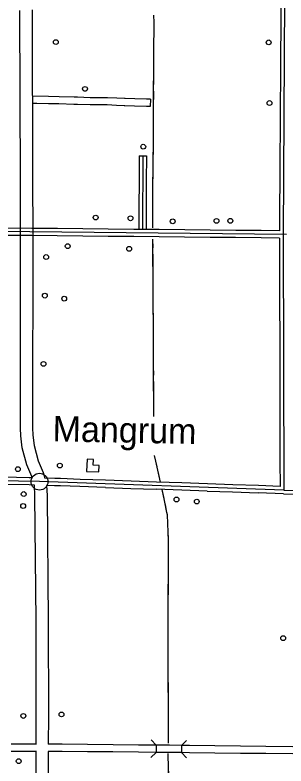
# Model space of a CAD drawing. Extents: x -4306 to 3843, y 131 to 8341.
# Drawn here: x -1173 to -274, y 4435 to 6927 of the extents above; entities that cross this region are included whole.
import ezdxf

# ---------------------------------------------------------------- set-up
doc = ezdxf.new("R2010")
doc.units = 0
for name, color, linetype in [('10', 7, 'Continuous'), ('24', 7, 'Continuous'), ('31', 7, 'Continuous'), ('32', 7, 'Continuous'), ('38', 7, 'Continuous'), ('56', 7, 'Continuous'), ('57', 7, 'Continuous'), ('60', 7, 'Continuous')]:
    doc.layers.add(name, color=color, linetype=linetype)

msp = doc.modelspace()

# ---------------------------------------------------------------- linework, layer by layer
at = {"layer": '10'}
for p, q in [((-1154.7, 6376.4), (-1156.2, 6941.8)), ((-1116.2, 6944.1), (-1114.6, 6374.8))]:
    msp.add_line(p, q, dxfattribs=at)
for points in [[(-1115.9, 5392.1), (-1117, 5396), (-1133.5, 5434.2), (-1148.9, 5491), (-1153.2, 5529.9), (-1154.3, 5556.1), (-1153.9, 6206.8), (-1154.7, 6376.4)], [(-1114.6, 6374.8), (-1113.9, 6206.9), (-1114.3, 5556.9), (-1113.3, 5533), (-1109.5, 5498.5), (-1095.6, 5447.4), (-1079.2, 5409.3), (-1073.9, 5390.1)], [(-1102.4, 4507.2), (-1102, 4600.1), (-1102.8, 4916.5), (-1106.4, 5331), (-1107.8, 5367)], [(-1067.7, 5365.9), (-1066.4, 5331.9), (-1062.8, 4916.7), (-1062, 4600.1), (-1062.4, 4507.1)], [(-1101.9, 4080.9), (-1103.3, 4295.8), (-1102.5, 4483.2)], [(-1062.5, 4483.1), (-1063.3, 4295.8), (-1061.9, 4081.1)]]:
    msp.add_lwpolyline(points, dxfattribs=at)
at = {"layer": '24'}
msp.add_circle((-1091.3, 5378.3), 28, dxfattribs=at)
at = {"layer": '31'}
for p, q in [((-1041, 5389), (-1073.9, 5390.1)), ((-1021.2, 5388.3), (-1041, 5389)), ((-956.5, 5386), (-1021.2, 5388.3)), ((-872.1, 5383.1), (-956.5, 5386)), ((-1041.8, 5365), (-1067.7, 5365.9)), ((-1022, 5364.3), (-1041.8, 5365)), ((-957.4, 5362), (-1022, 5364.3)), ((-872.9, 5359.1), (-957.4, 5362)), ((-618.8, 5374.2), (-703.2, 5377.2)), ((-534.3, 5371.2), (-618.8, 5374.2)), ((-293.5, 5362.8), (-365.5, 5365.3)), ((-704, 5353.2), (-704, 5353.2)), ((-619.6, 5350.2), (-704, 5353.2)), ((-535.2, 5347.3), (-619.6, 5350.2)), ((-366.3, 5341.3), (-366.3, 5341.3)), ((-281.9, 5338.4), (-366.3, 5341.3)), ((-281.8, 5338.4), (-244.9, 5337.3))]:
    msp.add_line(p, q, dxfattribs=at)
for points in [[(-872.9, 5359.1), (-788.5, 5356.1)], [(-787.6, 5380.1), (-872.1, 5383.1)], [(-703.2, 5377.2), (-787.6, 5380.1)], [(-449.9, 5368.3), (-534.3, 5371.2)], [(-365.5, 5365.3), (-449.9, 5368.3)], [(-788.5, 5356.1), (-704, 5353.2)], [(-535.2, 5347.3), (-450.7, 5344.3)], [(-450.7, 5344.3), (-366.3, 5341.3)]]:
    msp.add_lwpolyline(points, dxfattribs=at)
at = {"layer": '32'}
for p, q in [((-277.8, 7052), (-283.5, 6198.8)), ((-290.4, 6967.6), (-290.9, 6883.1)), ((-290.9, 6883.1), (-291.5, 6798.6)), ((-291.5, 6798.6), (-292, 6714.1)), ((-292, 6714.1), (-292.6, 6629.7)), ((-1061.1, 6656.6), (-1115.4, 6657.9)), ((-1026, 6655.7), (-1061.1, 6656.6)), ((-976.6, 6654.2), (-1026, 6655.7)), ((-965, 6653.9), (-976.6, 6654.2)), ((-1100.4, 6633.6), (-1115.4, 6633.8)), ((-1061.7, 6632.6), (-1100.4, 6633.6)), ((-1026.7, 6631.7), (-1061.7, 6632.6)), ((-977.3, 6630.2), (-1026.7, 6631.7)), ((-965.7, 6629.9), (-977.3, 6630.2)), ((-923.3, 6628.7), (-965.7, 6629.9)), ((-922.9, 6652.7), (-965, 6653.9)), ((-892.5, 6652.7), (-922.9, 6652.7)), ((-865.8, 6652.7), (-892.5, 6652.7)), ((-835.2, 6650.9), (-865.8, 6652.7)), ((-809.1, 6649.6), (-835.2, 6650.9)), ((-807.6, 6649.5), (-809.1, 6649.6)), ((-775.6, 6648.3), (-807.6, 6649.5)), ((-736, 6647.9), (-775.6, 6648.3)), ((-723, 6647.2), (-736, 6647.9)), ((-723, 6647.2), (-724.2, 6623.3)), ((-292.6, 6629.7), (-293.2, 6545.2)), ((-892.5, 6628.7), (-923.3, 6628.7)), ((-866.5, 6628.7), (-892.5, 6628.7)), ((-836.4, 6626.9), (-866.5, 6628.7)), ((-810.2, 6625.6), (-836.4, 6626.9)), ((-808.5, 6625.6), (-810.2, 6625.6)), ((-776.2, 6624.3), (-808.5, 6625.6)), ((-736.7, 6623.9), (-776.2, 6624.3)), ((-724.2, 6623.3), (-736.7, 6623.9)), ((-293.2, 6545.2), (-293.7, 6460.7)), ((-760.9, 6459.9), (-761.3, 6375.4)), ((-760.9, 6459.9), (-736.9, 6459.8)), ((-748.9, 6459.9), (-750.1, 6218.7)), ((-736.9, 6459.8), (-737.3, 6375.3)), ((-293.7, 6460.7), (-294.3, 6376.2)), ((-761.3, 6375.4), (-761.7, 6290.9)), ((-737.3, 6375.3), (-737.7, 6290.8)), ((-294.3, 6376.2), (-294.9, 6291.7)), ((-761.7, 6290.9), (-762.1, 6218.8)), ((-737.7, 6290.8), (-738.1, 6218.7)), ((-294.9, 6291.7), (-295.4, 6210.8)), ((-271.9, 6198.6), (-1756.9, 6213.2)), ((-1116.6, 6218.9), (-1201.1, 6219.7)), ((-1032.1, 6218), (-1116.6, 6218.9)), ((-947.6, 6217.2), (-1032.1, 6218)), ((-863.2, 6216.4), (-947.6, 6217.2)), ((-778.7, 6215.5), (-863.2, 6216.4)), ((-694.2, 6214.7), (-778.7, 6215.5)), ((-609.7, 6213.9), (-694.2, 6214.7)), ((-525.2, 6213.1), (-609.7, 6213.9)), ((-440.7, 6212.2), (-525.2, 6213.1)), ((-356.2, 6211.4), (-440.7, 6212.2)), ((-295.4, 6210.8), (-356.2, 6211.4)), ((-1116.8, 6194.9), (-1201.3, 6195.7)), ((-1032.4, 6194), (-1116.8, 6194.9)), ((-947.9, 6193.2), (-1032.4, 6194)), ((-863.4, 6192.4), (-947.9, 6193.2)), ((-778.9, 6191.5), (-863.4, 6192.4)), ((-694.4, 6190.7), (-778.9, 6191.5)), ((-609.9, 6189.9), (-694.4, 6190.7)), ((-525.5, 6189.1), (-609.9, 6189.9)), ((-441, 6188.2), (-525.5, 6189.1)), ((-356.5, 6187.4), (-441, 6188.2)), ((-295.5, 6186.8), (-356.5, 6187.4)), ((-295.5, 6186.8), (-295.3, 6122.6)), ((-283.5, 6198.8), (-281.4, 5350.4)), ((-295.3, 6122.6), (-295.1, 6038.1)), ((-295.1, 6038.1), (-294.9, 5953.7)), ((-294.9, 5953.7), (-294.7, 5869.2)), ((-294.7, 5869.2), (-294.5, 5784.7)), ((-294.5, 5784.7), (-294.3, 5700.2)), ((-294.3, 5700.2), (-294.1, 5615.7)), ((-294.1, 5615.7), (-293.9, 5531.2)), ((-293.9, 5531.2), (-293.7, 5446.7)), ((-293.7, 5446.7), (-293.5, 5362.8)), ((-1091.2, 5378.7), (-1896.6, 5393.4)), ((-1125.6, 5391.4), (-1210.1, 5392.9)), ((-1116.2, 5391.2), (-1125.6, 5391.4)), ((-1126, 5367.4), (-1210.5, 5368.9)), ((-1107.8, 5367), (-1126, 5367.4)), ((-281.4, 5350.4), (-1091.2, 5378.7)), ((-281.4, 5350.4), (-232.8, 5349)), ((-1100.9, 4507.2), (-1185.4, 4507.3)), ((-1016.3, 4506.7), (-1062.4, 4507.1)), ((-931.9, 4505.9), (-1016.3, 4506.7)), ((-847.4, 4505.2), (-931.9, 4505.9)), ((-762.9, 4504.4), (-847.4, 4505.2)), ((-704.4, 4503.9), (-762.9, 4504.4)), ((-704.4, 4504.1), (-704.7, 4480.1)), ((-678.4, 4503.7), (-704.4, 4503.9)), ((-659.7, 4503.5), (-678.4, 4503.7)), ((-620.5, 4503.1), (-659.7, 4503.5)), ((-620.5, 4503.1), (-620.7, 4479.1)), ((-593.9, 4502.7), (-620.5, 4503.1)), ((-509.4, 4501.7), (-593.9, 4502.7)), ((-424.9, 4500.7), (-509.4, 4501.7)), ((-340.4, 4499.7), (-424.9, 4500.7)), ((-251.2, 4498.7), (-340.4, 4499.7)), ((-1100.9, 4483.2), (-1185.4, 4483.3)), ((-1016.6, 4482.7), (-1062.5, 4483.1)), ((-932.1, 4481.9), (-1016.6, 4482.7)), ((-847.6, 4481.2), (-932.1, 4481.9)), ((-763.1, 4480.4), (-847.6, 4481.2)), ((-704.7, 4479.9), (-763.1, 4480.4)), ((-678.6, 4479.7), (-704.7, 4479.9)), ((-660, 4479.5), (-678.6, 4479.7)), ((-620.7, 4479.1), (-660, 4479.5)), ((-594.2, 4478.7), (-620.7, 4479.1)), ((-509.7, 4477.7), (-594.2, 4478.7)), ((-425.2, 4476.7), (-509.7, 4477.7)), ((-340.7, 4475.7), (-425.2, 4476.7)), ((-251.3, 4474.7), (-340.7, 4475.7))]:
    msp.add_line(p, q, dxfattribs=at)
at = {"layer": '38'}
for points in [[(-721.2, 4521.1), (-704.4, 4503.9)], [(-620.5, 4503.1), (-603.3, 4519.8)], [(-704.7, 4479.9), (-721.8, 4463.1)], [(-603.9, 4461.9), (-620.7, 4479.1)]]:
    msp.add_lwpolyline(points, dxfattribs=at)
at = {"layer": '56'}
for points in [[(-715.1, 6220.7), (-715.1, 6343.3), (-714.7, 6422.2), (-712.8, 6503.4), (-713.1, 6617.6), (-711.6, 6801), (-711.5, 6901.8), (-712, 6926.9)], [(-711.5, 6864.9), (-711.5, 6901.8), (-712, 6926.9)], [(-711.8, 6780.4), (-711.6, 6801), (-711.6, 6843.8)], [(-712.2, 6727.6), (-712, 6759.3)], [(-712.4, 6695.9), (-712.2, 6727.6)], [(-713, 6611.4), (-713.1, 6617.6), (-712.6, 6674.8)], [(-712.9, 6526.9), (-713, 6590.3)], [(-714.2, 6442.5), (-712.8, 6503.4), (-712.8, 6505.8)], [(-715.1, 6358), (-714.7, 6421.4)], [(-715.1, 6273.5), (-715.1, 6336.9)], [(-715.1, 6220.7), (-715.1, 6252.4)], [(-712, 5594.9), (-712.7, 5761.9), (-712.9, 5877.8), (-714.5, 5999.7), (-715, 6183.2)], [(-714.9, 6154.6), (-715, 6183.2)], [(-714.8, 6101.8), (-714.9, 6133.5)], [(-714.7, 6070.1), (-714.8, 6101.8)], [(-714.3, 5985.6), (-714.5, 5999.7), (-714.6, 6049)], [(-713.2, 5901.2), (-714, 5964.5)], [(-712.8, 5816.7), (-712.9, 5877.8), (-712.9, 5880)], [(-712.6, 5732.2), (-712.7, 5761.9), (-712.8, 5795.6)], [(-712.2, 5647.7), (-712.5, 5711.1)], [(-712, 5594.9), (-712.2, 5626.6)], [(-690, 5376.7), (-705.5, 5446.7), (-709.4, 5464.8)], [(-701.4, 5428.3), (-705.5, 5446.7), (-709.4, 5464.8)], [(-690, 5376.7), (-696.9, 5407.6)], [(-664, 4510.8), (-663.1, 4574.9), (-664.4, 4780.1), (-664.5, 4897), (-663.2, 5181.9), (-666.9, 5268.2), (-668.6, 5276.5), (-676.6, 5316), (-684.7, 5352.5)], [(-678.1, 5322.8), (-684.7, 5352.5)], [(-665.7, 5239.5), (-666.9, 5268.2), (-668.6, 5276.5), (-673.8, 5302.2)], [(-663.4, 5155.1), (-663.2, 5181.9), (-664.8, 5218.4)], [(-663.7, 5070.6), (-663.5, 5133.9)], [(-664, 5017.8), (-663.8, 5049.4)], [(-664.1, 4986.1), (-664, 5017.8)], [(-664.5, 4901.6), (-664.2, 4965)], [(-664.4, 4817.1), (-664.5, 4880.5)], [(-664.1, 4732.6), (-664.4, 4780.1), (-664.4, 4796)], [(-663.6, 4648.1), (-663.9, 4711.5)], [(-663.2, 4563.6), (-663.1, 4574.9), (-663.4, 4627)], [(-664, 4510.8), (-663.5, 4542.5)], [(-664.9, 3658.3), (-664.8, 3769), (-664.2, 3999.1), (-663.1, 4070.7), (-663.3, 4248.8), (-662.5, 4377), (-664.1, 4475.7)], [(-662.7, 4387), (-663.7, 4450.4)]]:
    msp.add_lwpolyline(points, dxfattribs=at)
at = {"layer": '57'}
for centre in [(-1037.1, 6837.1), (-331.2, 6836.2), (-940.4, 6681.8), (-328.3, 6634.8), (-747.2, 6489.9), (-905, 6254.8), (-789.7, 6252.5), (-649.5, 6242.3), (-504.4, 6243.7), (-458.3, 6244), (-997.8, 6160), (-794.1, 6151.1), (-1069.2, 6123.7), (-1073.5, 5995.8), (-1009.3, 5985.6), (-1078.2, 5769.2), (-1023.9, 5431.7), (-1163, 5419.7), (-1143.7, 5337.2), (-636.8, 5319.1), (-569.7, 5312.3), (-1145.6, 5297.5), (-283.2, 4858.8), (-1018.3, 4605.9), (-1144.9, 4600.9), (-1160.3, 4450.6)]:
    msp.add_circle(centre, 8, dxfattribs=at)
at = {"layer": '60'}
msp.add_lwpolyline([(-935.6, 5412.5), (-895, 5410.5), (-894, 5432), (-913.2, 5432.9), (-912.2, 5452.1), (-933.6, 5453.1)], close=True, dxfattribs=at)

# ---------------------------------------------------------------- texts
at = {"layer": '24'}
msp.add_text('Mangrum', height=84.49, rotation=358.9554, dxfattribs=at).set_placement((-1048.6, 5512.1))

doc.saveas('drawing.dxf')
